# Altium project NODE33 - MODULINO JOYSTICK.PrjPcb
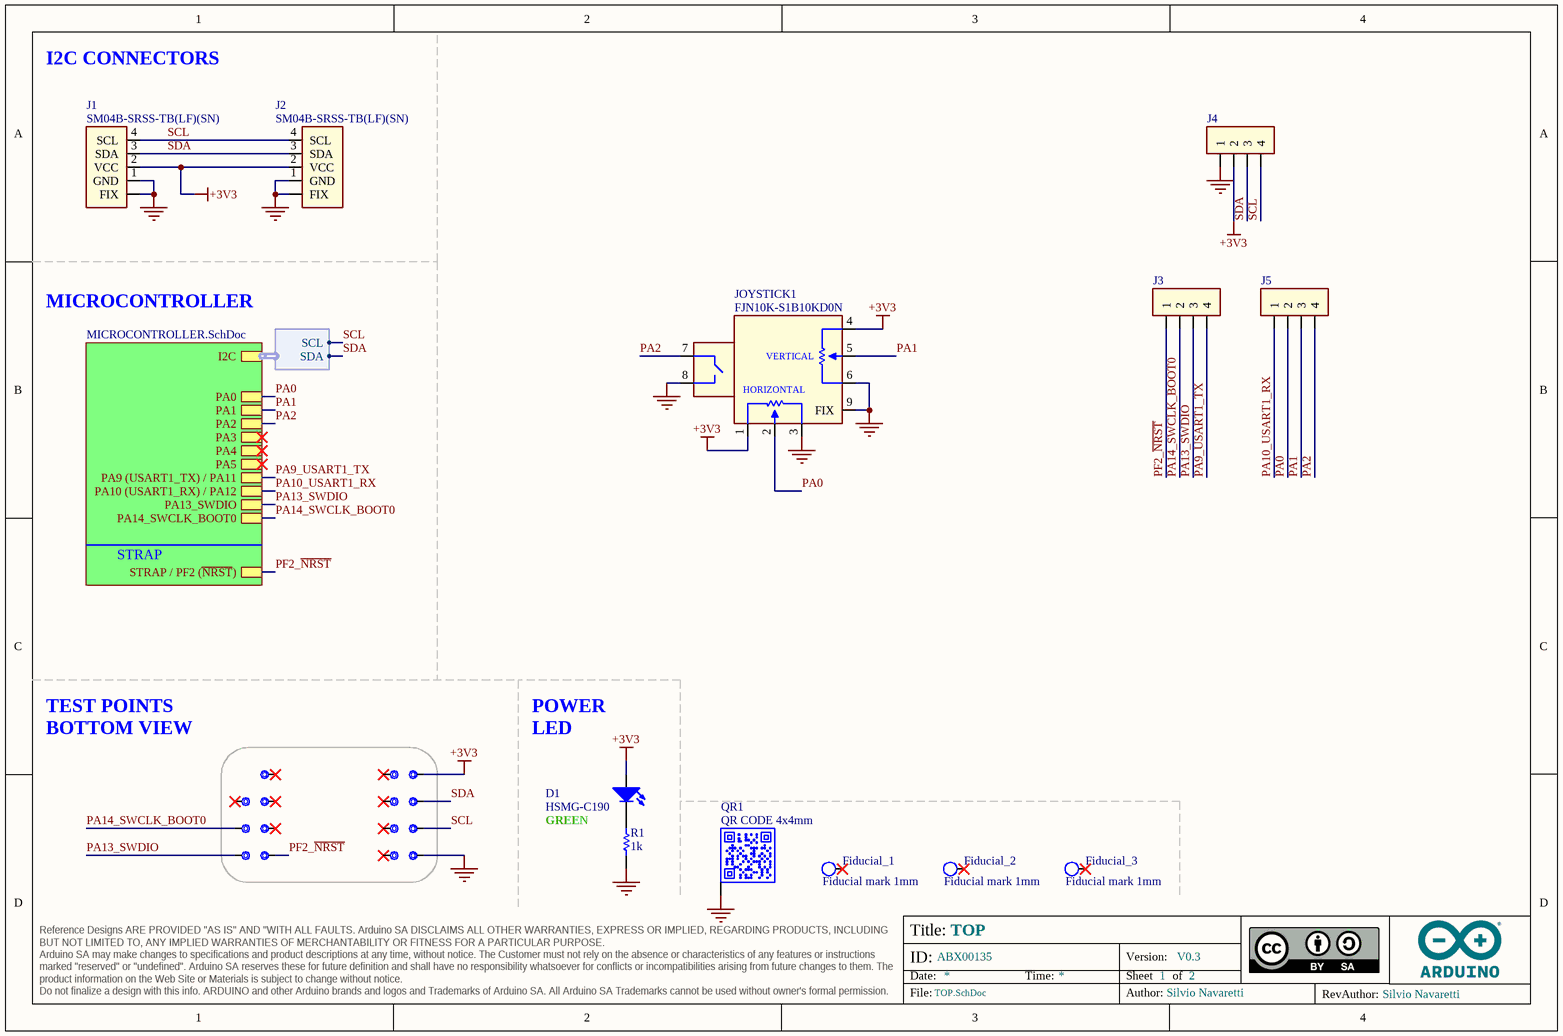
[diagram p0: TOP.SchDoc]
ASSEMBLY_BGA: _; ASSEMBLY_PRESSFIT: _; ASSEMBLY_SMD: X; ASSEMBLY_THT: X; BOARD_CODENAME: NODE33 MODULINO JOYSTICK; BOARD_INFO_AUTHOR: Silvio Navaretti; BOARD_INFO_AUTHOR_REV: Silvio Navaretti; BOARD_INFO_Er: _; BOARD_INFO_FLEX: _; BOARD_INFO_FR4: X; BOARD_INFO_FR4_HTG: _; BOARD_INFO_IPC1: _; BOARD_INFO_IPC2: X; BOARD_INFO_IPC3: _; BOARD_INFO_IPC_NA: _; BOARD_INFO_NUMBER_OF_LAYERS: 2; BOARD_INFO_PCB_SIZE: 41.00x25.36mm; BOARD_INFO_POLYMIDE: _; BOARD_INFO_RIGID: X; BOARD_INFO_RIGID/FLEX: _; BOARD_INFO_TBD: _; BOARD_INFO_THICKNESS: 1.6mm; DRILLS_BLIND: _; DRILLS_BURIED: _; DRILLS_COPPER_FILLING: _; DRILLS_FULL: X; DRILLS_LASER: _; DRILLS_PRESSFIT: _; DRILLS_RESIN_FILLING: _; DRILLS_SLOT: _; DRILLS_SOLDER_FILLING: X; FINISH_ADJUSTMENTS: _; FINISH_EDGE_PLATING: _; FINISH_ENIG: _; FINISH_HAL: _; FINISH_HAL_LF: X; FINISH_NI/AU: _; FINISH_SILK_BOTTOM: X; FINISH_SILK_COLOR: WHITE; FINISH_SILK_TOP: X; FINISH_SN/PB: _; FINISH_SOLDERMASK_BOTTOM: X; FINISH_SOLDERMASK_COLOR: BLUE; FINISH_SOLDERMASK_PEELABLE_BOTTOM: _; FINISH_SOLDERMASK_PEELABLE_COLOR: _; FINISH_SOLDERMASK_PEELABLE_TOP: _; FINISH_SOLDERMASK_TOP: X; FINISH_TABS: _; FINISH_TBD: _; INSULATION_MIN_INNER: 0.15mm; INSULATION_MIN_OUTER: 0.15mm; PANEL_MILLING: X; PANEL_NOT_REQUESTED: _; PANEL_NUMBER_OF_FIGURES: 30; PANEL_PROVIDED: X; PANEL_REQUESTED: _; PANEL_SCORING: X; PANEL_SIZE: 262.00x221.00mm; PANEL_TABS: _; SKU: ABX00135; TRACK_MIN_WIDTH_INNER: 0.15mm; TRACK_MIN_WIDTH_OUTER: 0.15mm; Version: V0.3; VIA_1: _; VIA_1_HOLE_MM: _; VIA_1_PAD_MM: _; VIA_2: _; VIA_2_HOLE_MM: _; VIA_2_PAD_MM: _; VIA_3: _; VIA_3_HOLE_MM: _; VIA_3_PAD_MM: _; VIA_4: _; VIA_4_HOLE_MM: _; VIA_4_PAD_MM: _; VIA_5: _; VIA_5_HOLE_MM: _; VIA_5_PAD_MM: _; VIA_THROUGH: X; VIA_THROUGH_HOLE_MM: 0.3; VIA_THROUGH_PAD_MM: 0.6
2 sheets, 38 parts. Net scope: hierarchical (ports join the sheet entries above them; power ports are global).
Board files: PCB.PcbDoc, PANEL.PcbDoc
Sheets:
  TOP.SchDoc
    U_MICROCONTROLLER = MICROCONTROLLER.SchDoc

## Sheet TOP.SchDoc: TOP
size A4; Revision: V0.3; SheetNumber: 1; SheetTotal: 2

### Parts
3V3  Test point 1.00mm  [TP-1.00MM]  (value not drawn)  (no BOM)
D1  HSMG-C190  [LEDC1608X80N-AK]
Fiducial_1  Fiducial mark 1mm  [Fiducial mark 1mm-Footprint-1]  (no BOM)
Fiducial_2  Fiducial mark 1mm  [Fiducial mark 1mm-Footprint-1]  (no BOM)
Fiducial_3  Fiducial mark 1mm  [Fiducial mark 1mm-Footprint-1]  (no BOM)
GND  Test point 1.00mm  [TP-1.00MM]  (value not drawn)  (no BOM)
J1  SM04B-SRSS-TB(LF)(SN)  [SM04B-SRSS-TB(LF)(SN)-Footprint-1]
J2  SM04B-SRSS-TB(LF)(SN)  [SM04B-SRSS-TB(LF)(SN)-Footprint-1]
J3  HEADER TH 2.54mm VERT. 1x004POS  [PIN HEADER 2.54mm VERT. 1x4POS-Footprint-1]  (value not drawn)  (no BOM)
J4  HEADER TH 2.54mm VERT. 1x004POS  [PIN HEADER 2.54mm VERT. 1x4POS-Footprint-1]  (value not drawn)  (no BOM)
J5  HEADER TH 2.54mm VERT. 1x004POS  [PIN HEADER 2.54mm VERT. 1x4POS-Footprint-1]  (value not drawn)  (no BOM)
JOYSTICK1  FJN10K-S1B10KD0N  [FJN10K-S1B10KD0N]
NRST  Test point 1.00mm  [TP-1.00MM]  (value not drawn)  (no BOM)
PA6  Test point 1.00mm  [TP-1.00MM]  (value not drawn)  (no BOM)
PA7  Test point 1.00mm  [TP-1.00MM]  (value not drawn)  (no BOM)
PC14  Test point 1.00mm  [TP-1.00MM]  (value not drawn)  (no BOM)
PC15  Test point 1.00mm  [TP-1.00MM]  (value not drawn)  (no BOM)
QR1  QR CODE 4x4mm  [QR CODE 4x4mm]  (no BOM)
R1  value 1k  [RES-0402]  (hidden comment: CRCW04021K00FKEDC)
SCL  Test point 1.00mm  [TP-1.00MM]  (value not drawn)  (no BOM)
SDA  Test point 1.00mm  [TP-1.00MM]  (value not drawn)  (no BOM)
SWCLK  Test point 1.00mm  [TP-1.00MM]  (value not drawn)  (no BOM)
SWDIO  Test point 1.00mm  [TP-1.00MM]  (value not drawn)  (no BOM)
TP9  Test point 1.00mm  [TP-1.00MM]  (value not drawn)  (no BOM)
TP10  Test point 1.00mm  [TP-1.00MM]  (value not drawn)  (no BOM)
TP11  Test point 1.00mm  [TP-1.00MM]  (value not drawn)  (no BOM)
TP12  Test point 1.00mm  [TP-1.00MM]  (value not drawn)  (no BOM)

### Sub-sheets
U_MICROCONTROLLER = MICROCONTROLLER.SchDoc: I2C (harness I2C), PA0, PA1, PA2, PA3, PA4, PA5, PA13_SWDIO, PA14_SWCLK_BOOT0, PA9 (USART1_TX) / PA11, PA10 (USART1_RX) / PA12, STRAP / PF2 (~{NRST})

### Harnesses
I2C: SDA, SCL

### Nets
+3V3: 3V3.X D1.A J1.2(VCC) J2.2(VCC) J4.2 JOYSTICK1.1 JOYSTICK1.4
GND: GND.X J1.1(GND) J1.FIX J2.1(GND) J2.FIX J4.1 JOYSTICK1.3 JOYSTICK1.6 JOYSTICK1.8 JOYSTICK1.9(FIX) QR1.PAD R1.1
PA0: J5.2 JOYSTICK1.2 ; sheet U_MICROCONTROLLER/PA0
PA1: J5.3 JOYSTICK1.5 ; sheet U_MICROCONTROLLER/PA1
PA2: J5.4 JOYSTICK1.7 ; sheet U_MICROCONTROLLER/PA2
PA9_USART1_TX: J3.4 ; sheet U_MICROCONTROLLER/PA9 (USART1_TX) / PA11
PA10_USART1_RX: J5.1 ; sheet U_MICROCONTROLLER/PA10 (USART1_RX) / PA12
PA13_SWDIO: J3.3 SWCLK.X ; sheet U_MICROCONTROLLER/PA13_SWDIO
PA14_SWCLK_BOOT0: J3.2 SWDIO.X ; sheet U_MICROCONTROLLER/PA14_SWCLK_BOOT0
PF2_~{NRST}: J3.1 NRST.X ; sheet U_MICROCONTROLLER/STRAP / PF2 (~{NRST})
SCL: J1.4(SCL) J2.4(SCL) J4.4 SCL.X ; sheet U_MICROCONTROLLER/I2C.SCL
SDA: J1.3(SDA) J2.3(SDA) J4.3 SDA.X ; sheet U_MICROCONTROLLER/I2C.SDA
NetD1_C: D1.C R1.2

Not connected (* = marked no-connect by the designer): Fiducial_1 1*; Fiducial_2 1*; Fiducial_3 1*; PA6 X*; PA7 X*; PC14 X*; PC15 X*; TP9 X*; TP10 X*; TP11 X*; TP12 X*

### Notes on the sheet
- I2C CONNECTORS
- MICROCONTROLLER
- STRAP
- TEST POINTS BOTTOM VIEW
- (near D1) POWER LED
- GREEN

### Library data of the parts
3V3 GND NRST PA6 PA7 PC14 PC15 SCL SDA SWCLK SWDIO TP9-TP12 = UT0013-A.6: Manufacturer: This is not a component
D1 = L0009-A.5: LED SMD 0603 GREEN/568 15mcd 120^; Manufacturer: Broadcom; Code Arduino: 2204
Fiducial_1-Fiducial_3 = UT0023-A.7: Fiducial mark 1mm clearance 2mm
J1 J2 = J0005-A.2: CONN JST 4POS SIDE 1MM TIN QWIIC; Code Arduino: J0005
J3-J5 = J0162-A.6: Code Arduino: J0162
JOYSTICK1 = S0066-A.4: Joystick 10kR 20%, max 5V, with switch 12V 50mA max 100mR; Manufacturer: FAVOR ELECTRONICS(DONG GUAN)CO., LTD.; Code Arduino: S0066
QR1 = QR-0001-A.5: QR CODE 4x4mm on layer 34 (This is not a component); Code Arduino: QRCODE_4x4mm
R1 = R0007-A.24: RES CHIP 0402 1k 1% 1/16W; Manufacturer: Vishay; Code Arduino: 0140; Power: 62.5mW; Temperature coefficient: 100ppm

## Sheet MICROCONTROLLER.SchDoc: MICROCONTROLLER
size A4; SheetNumber: 2; SheetTotal: 2
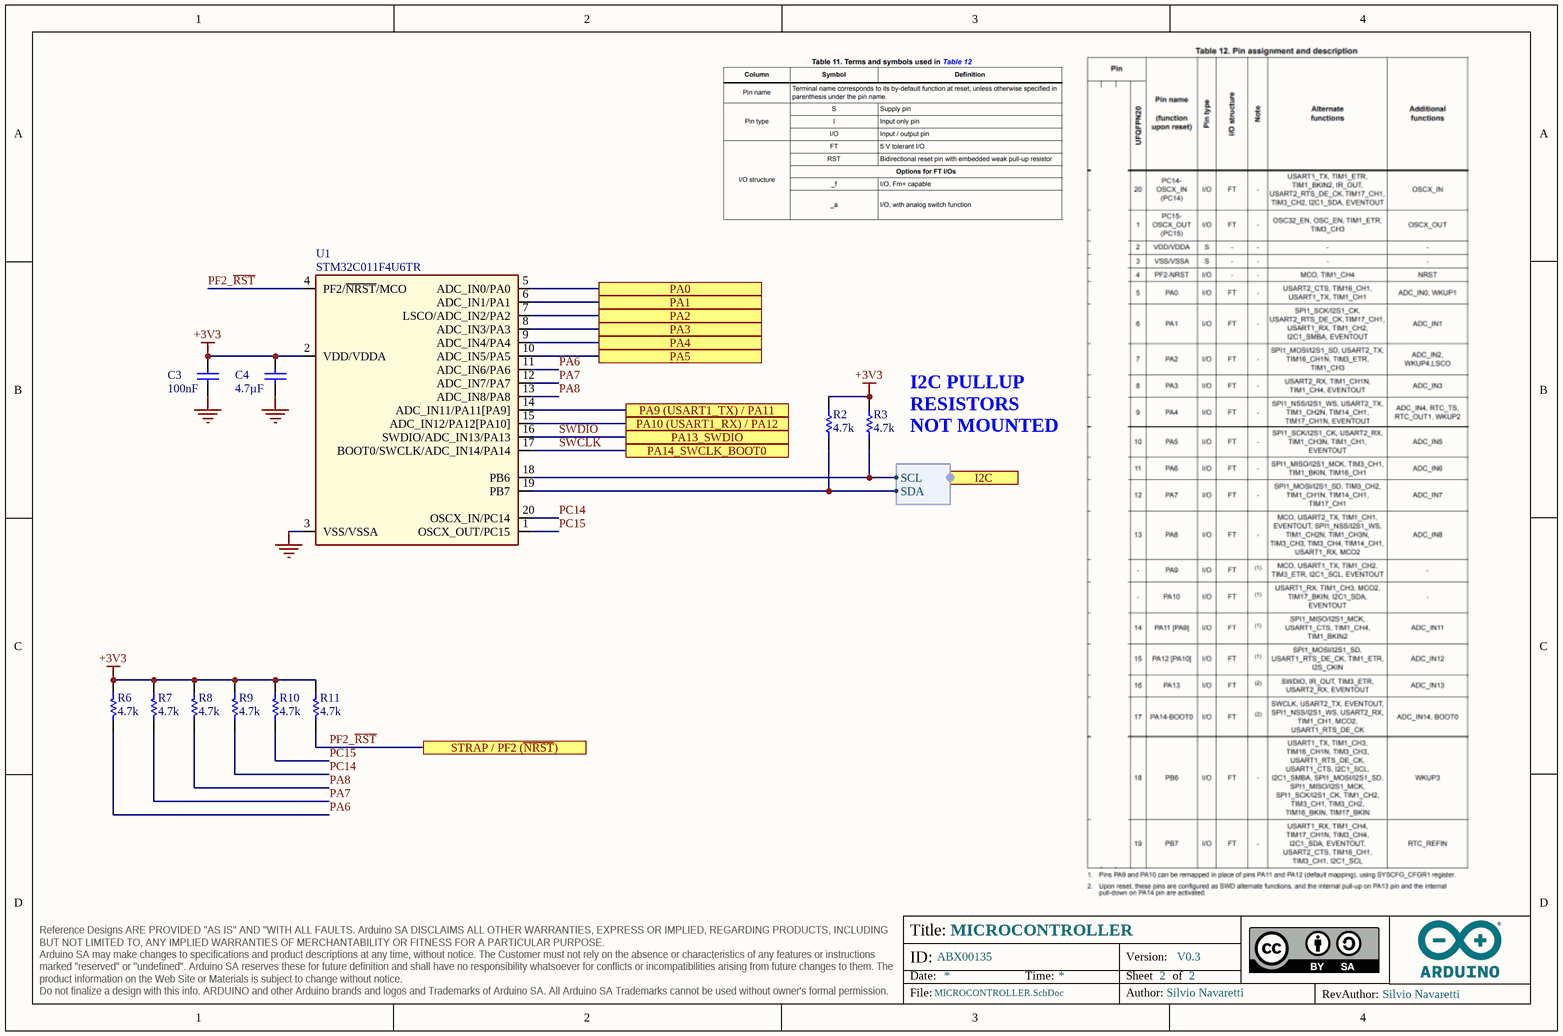
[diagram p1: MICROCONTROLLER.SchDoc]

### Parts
C3  value 100nF  [CAP-0402]  (hidden comment: 0402B104K160CT)
C4  value 4.7µF  [CAP-0603]  (hidden comment: GRM188R61C475KAAJD)
R2  value 4.7k  [RES-0402]  (hidden comment: RC0402FR-074K7L)
R3  value 4.7k  [RES-0402]  (hidden comment: RC0402FR-074K7L)
R6  value 4.7k  [RES-0402]  (hidden comment: RC0402FR-074K7L)
R7  value 4.7k  [RES-0402]  (hidden comment: RC0402FR-074K7L)
R8  value 4.7k  [RES-0402]  (hidden comment: RC0402FR-074K7L)
R9  value 4.7k  [RES-0402]  (hidden comment: RC0402FR-074K7L)
R10  value 4.7k  [RES-0402]  (hidden comment: RC0402FR-074K7L)
R11  value 4.7k  [RES-0402]  (hidden comment: RC0402FR-074K7L)
U1  STM32C011F4U6TR  [UFQFPN20]

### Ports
I2C (harness I2C), PA0, PA1, PA2, PA3, PA4, PA5, PA9 (USART1_TX) / PA11, PA10 (USART1_RX) / PA12, PA13_SWDIO, PA14_SWCLK_BOOT0, STRAP / PF2 (~{NRST})

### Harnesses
I2C: SDA, SCL

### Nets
+3V3: C3.1 C4.2 R2.2 R3.2 R6.1 R7.1 R8.1 R9.1 R10.1 R11.1 U1.2(VDD/VDDA)
GND: C3.2 C4.1 U1.3(VSS/VSSA)
PA0: U1.5(ADC_IN0/PA0) ; port PA0
PA1: U1.6(ADC_IN1/PA1) ; port PA1
PA2: U1.7(LSCO/ADC_IN2/PA2) ; port PA2
PA6: R6.2 U1.11(ADC_IN6/PA6)  [project net PA6_2]
PA7: R7.2 U1.12(ADC_IN7/PA7)  [project net PA7_2]
PA8: R8.2 U1.13(ADC_IN8/PA8)  [project net PA8_2]
PA9_USART1_TX: U1.14(ADC_IN11/PA11[PA9]) ; port PA9 (USART1_TX) / PA11
PA10_USART1_RX: U1.15(ADC_IN12/PA12[PA10]) ; port PA10 (USART1_RX) / PA12
PC14: R9.2 U1.20(OSCX_IN/PC14)  [project net PC14_2]
PC15: R10.2 U1.1(OSCX_OUT/PC15)  [project net PC15_2]
PF2_~{RST}: R11.2 U1.4(PF2/~{NRST}/MCO) ; port STRAP / PF2 (~{NRST})  [project net PF2_~{NRST}]
SCL: R3.1 U1.18(PB6) ; port I2C.SCL
SDA: R2.1 U1.19(PB7) ; port I2C.SDA
SWCLK: U1.17(BOOT0/SWCLK/ADC_IN14/PA14) ; port PA14_SWCLK_BOOT0  [project net PA14_SWCLK_BOOT0]
SWDIO: U1.16(SWDIO/ADC_IN13/PA13) ; port PA13_SWDIO  [project net PA13_SWDIO]
NetU1_8: U1.8(ADC_IN3/PA3) ; port PA3
NetU1_9: U1.9(ADC_IN4/PA4) ; port PA4
NetU1_10: U1.10(ADC_IN5/PA5) ; port PA5

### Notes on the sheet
- (near R3) I2C PULLUP RESISTORS NOT MOUNTED

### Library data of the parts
C3 = C0012-A.15: CAP CHIP 0402 100nF 10% 16V X7R; Manufacturer: Walsin; Code Arduino: 0132
C4 = C0054-A.16: CAP CHIP 0603 4.7uF 10% 16V X5R; Manufacturer: Murata; Code Arduino: A5072
R2 R3 = R0013-A.24: RES CHIP 0402 4k7 1% 1/16W; Manufacturer: YAGEO; Code Arduino: 2196; Power: 62.5mW; Temperature coefficient: 200ppm
R6-R11 = R0013-A.24: RES CHIP 0402 4k7 1% 1/16W; Manufacturer: YAGEO; Power: 62.5mW; Code Arduino: 2196; Temperature coefficient: 200ppm
U1 = U0363-A.4: IC Cortex M0, 32b MCU, 16KB Flash, 6KB RAM, VDD 2-3.6V, -40°C to 85°C, QFN20 3x3mm; Manufacturer: ST Microelectronics; Code Arduino: U0363

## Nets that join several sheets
+3V3: TOP (7 pins), MICROCONTROLLER (11 pins)
GND: TOP (12 pins), MICROCONTROLLER (C3.2 C4.1 U1.3)
PA0: TOP (J5.2 JOYSTICK1.2), MICROCONTROLLER (U1.5)
PA1: TOP (J5.3 JOYSTICK1.5), MICROCONTROLLER (U1.6)
PA2: TOP (J5.4 JOYSTICK1.7), MICROCONTROLLER (U1.7)
PA9_USART1_TX: TOP (J3.4), MICROCONTROLLER (U1.14)
PA10_USART1_RX: TOP (J5.1), MICROCONTROLLER (U1.15)
PA13_SWDIO: TOP (J3.3 SWCLK.X), MICROCONTROLLER (U1.16)
PA14_SWCLK_BOOT0: TOP (J3.2 SWDIO.X), MICROCONTROLLER (U1.17)
PF2_~{NRST}: TOP (J3.1 NRST.X), MICROCONTROLLER (R11.2 U1.4)
SCL: TOP (J1.4 J2.4 J4.4 SCL.X), MICROCONTROLLER (R3.1 U1.18)
SDA: TOP (J1.3 J2.3 J4.3 SDA.X), MICROCONTROLLER (R2.1 U1.19)

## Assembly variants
ABX00135: not fitted R2 R3 R7 R10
